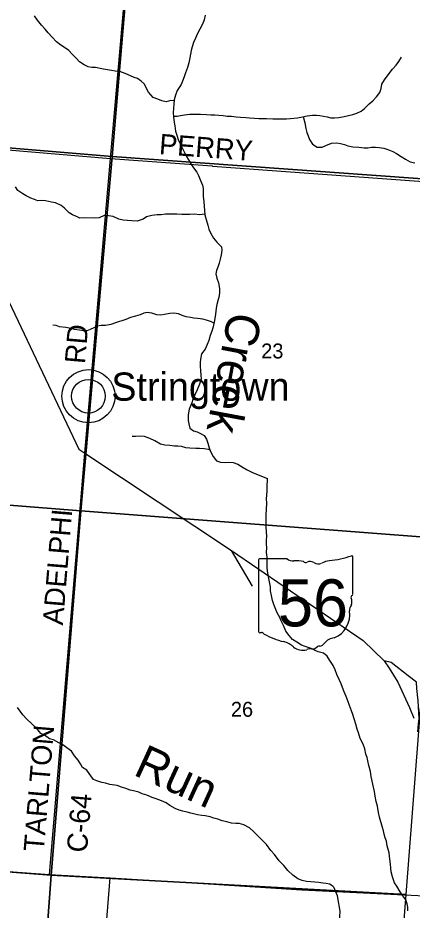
# Model space of a CAD drawing. Extents: x 1643459 to 2064572, y 425441 to 780708.
# Drawn here: x 1890096 to 1895923, y 540058 to 553249 of the extents above; entities that cross this region are included whole.
import ezdxf

# ---------------------------------------------------------------- set-up
doc = ezdxf.new("R2010")
doc.units = 0
for name, color, linetype in [('GE_P_Alignment_100_Curve_Data', 7, 'Continuous'), ('GM_X_Adjacent_County', 7, 'Continuous'), ('GM_X_Interchange_Ramps', 7, 'Continuous'), ('GM_X_Major_River', 7, 'Continuous'), ('GM_X_Major_River_Text', 7, 'Continuous'), ('GM_X_Minor_Lake', 7, 'Continuous'), ('GM_X_Rail_Line', 7, 'Continuous'), ('GM_X_Section_Text', 7, 'Continuous'), ('GM_X_State_Route', 7, 'Continuous'), ('GM_X_State_Shield', 7, 'Continuous'), ('GM_X_Township_ROW', 7, 'Continuous'), ('GM_X_Unincorporated_Text', 7, 'Continuous'), ('GM_X_US_Route', 7, 'Continuous'), ('PM_P_Cells', 7, 'Continuous'), ('RD_X_Text', 7, 'Continuous'), ('ST_Details', 7, 'Continuous')]:
    doc.layers.add(name, color=color, linetype=linetype)

msp = doc.modelspace()

# ---------------------------------------------------------------- linework, layer by layer
at = {"layer": 'GE_P_Alignment_100_Curve_Data'}
for radius in [393, 249]:
    msp.add_circle((1891139, 547656), radius, dxfattribs=at)
at = {"layer": 'GM_X_Major_River_Text'}
for points in [[(1888305, 551438), (1891467, 551170)], [(1891467, 551170), (1892970, 551059), (1892972, 551058)], [(1892972, 551058), (1901848, 550410)], [(1893566, 544847), (1893251, 545376)]]:
    msp.add_lwpolyline(points, dxfattribs=at)
at = {"layer": 'GM_X_Minor_Lake'}
for points in [[(1891088, 546815), (1891088, 546815), (1891467, 551170), (1891853, 555616)], [(1890566, 540586), (1891088, 546815)], [(1896005, 542692), (1896018, 542807), (1896027, 542889), (1896010, 543154), (1895992, 543336), (1895987, 543429), (1895862, 543523), (1895613, 543717), (1895512, 543746)], [(1877545, 541541), (1882763, 541167), (1885378, 540966), (1890566, 540586), (1891458, 540534), (1891546, 540529), (1892911, 540445), (1894292, 540358), (1896111, 540272)], [(1891039, 535264), (1891458, 540534)]]:
    msp.add_lwpolyline(points, dxfattribs=at)
at = {"layer": 'GM_X_Rail_Line'}
msp.add_line((1891139, 547656), (1891139, 547656), dxfattribs=at)
at = {"layer": 'GM_X_State_Route'}
for points in [[(1886800, 556947), (1891943, 556530), (1891491, 551199), (1886336, 551627)], [(1891943, 556530), (1897162, 556078), (1896690, 550827), (1891491, 551199)], [(1891491, 551199), (1891025, 545962), (1885858, 546368), (1886336, 551627)], [(1896690, 550827), (1896241, 545563), (1891025, 545962), (1891491, 551199)], [(1885858, 546368), (1891025, 545962), (1890589, 540577), (1885382, 540977)], [(1891025, 545962), (1896241, 545563), (1895832, 540288), (1890589, 540577)], [(1885382, 540977), (1890589, 540577), (1890205, 535356), (1890115, 535362), (1884902, 535726)], [(1890589, 540577), (1895832, 540288), (1895415, 535000), (1895294, 535008), (1890205, 535356)]]:
    msp.add_lwpolyline(points, close=True, dxfattribs=at)
at = {"layer": 'GM_X_Unincorporated_Text'}
for points in [[(1892865, 553289), (1892851, 553219), (1892828, 553165), (1892786, 553081), (1892753, 553019), (1892719, 552949), (1892690, 552885), (1892670, 552821), (1892656, 552765), (1892645, 552713), (1892637, 552657), (1892623, 552585), (1892601, 552517), (1892574, 552435), (1892552, 552379), (1892527, 552315), (1892509, 552265), (1892450, 552177), (1892426, 552107), (1892408, 552039), (1892400, 551975), (1892395, 551912), (1892393, 551844), (1892395, 551788), (1892407, 551702), (1892415, 551652), (1892427, 551573), (1892445, 551517), (1892467, 551453), (1892495, 551386), (1892527, 551320), (1892554, 551269), (1892582, 551211), (1892616, 551149), (1892654, 551090), (1892692, 551034), (1892739, 550967), (1892765, 550917), (1892795, 550846), (1892823, 550776), (1892833, 550726), (1892835, 550674), (1892837, 550615), (1892845, 550531), (1892851, 550467), (1892855, 550399), (1892858, 550337), (1892879, 550266), (1892905, 550182), (1892919, 550125), (1892943, 550069), (1892987, 549993), (1893039, 549934), (1893104, 549865), (1893112, 549813), (1893102, 549745), (1893085, 549683), (1893069, 549623), (1893053, 549565), (1893030, 549513), (1893022, 549463), (1893036, 549400), (1893060, 549334), (1893076, 549250), (1893076, 549200), (1893070, 549137), (1893056, 549083), (1893039, 549011), (1893025, 548955), (1893015, 548871), (1893001, 548777), (1892980, 548683), (1892962, 548619), (1892937, 548551), (1892917, 548481), (1892893, 548421), (1892862, 548351), (1892810, 548283), (1892793, 548205), (1892791, 548153), (1892791, 548098), (1892797, 548030), (1892801, 547968), (1892807, 547908), (1892782, 547836), (1892746, 547752), (1892713, 547676), (1892681, 547608)], [(1892681, 547608), (1892665, 547558), (1892626, 547466), (1892612, 547380), (1892614, 547299), (1892622, 547247), (1892638, 547183), (1892692, 547142), (1892744, 547128), (1892797, 547106), (1892847, 547075), (1892882, 547021), (1892904, 546960), (1892924, 546892), (1892944, 546838), (1892980, 546765), (1893030, 546701), (1893091, 546682), (1893158, 546678), (1893212, 546683), (1893279, 546675), (1893349, 546650), (1893426, 546604), (1893485, 546569), (1893545, 546536), (1893597, 546512), (1893784, 546439)], [(1895027, 543007), (1894999, 543083), (1894975, 543153), (1894947, 543216), (1894920, 543284), (1894896, 543350), (1894872, 543406), (1894846, 543467), (1894812, 543541), (1894784, 543613), (1894756, 543675), (1894706, 543750), (1894669, 543814), (1894611, 543857), (1894535, 543877), (1894479, 543903), (1894429, 543924), (1894340, 543954), (1894290, 543974), (1894218, 544019), (1894154, 544061), (1894105, 544116), (1894055, 544184), (1894023, 544266), (1893989, 544333), (1893967, 544383), (1893929, 544451), (1893907, 544505), (1893879, 544576), (1893859, 544638), (1893844, 544708), (1893830, 544778), (1893828, 544838), (1893820, 544889), (1893806, 544959), (1893790, 545039), (1893782, 545115), (1893779, 545179), (1893779, 545276), (1893773, 545344), (1893775, 545412), (1893773, 545472), (1893771, 545530), (1893774, 545586), (1893772, 545650), (1893768, 545723), (1893768, 545915), (1893769, 545971), (1893775, 546083), (1893773, 546135), (1893775, 546198), (1893779, 546254), (1893781, 546306), (1893784, 546439)], [(1895859, 540046), (1895859, 540100), (1895849, 540151), (1895832, 540209), (1895786, 540269), (1895748, 540327), (1895696, 540412), (1895662, 540462), (1895634, 540553), (1895612, 540627), (1895608, 540679), (1895604, 540739), (1895593, 540811), (1895583, 540908), (1895553, 541008), (1895543, 541076), (1895525, 541128), (1895511, 541180), (1895500, 541231), (1895486, 541281), (1895442, 541435), (1895426, 541502), (1895410, 541596), (1895392, 541666), (1895377, 541742), (1895369, 541810), (1895341, 541923), (1895317, 542035), (1895307, 542107), (1895284, 542198), (1895268, 542264), (1895256, 542314), (1895240, 542366), (1895224, 542441), (1895200, 542511), (1895156, 542597), (1895128, 542678), (1895113, 542732), (1895089, 542810), (1895067, 542886), (1895047, 542952), (1895027, 543007)]]:
    msp.add_lwpolyline(points, dxfattribs=at)
at = {"layer": 'GM_X_US_Route'}
for points in [[(1892406, 552023), (1892359, 552025), (1892286, 552008), (1892224, 552024), (1892165, 552045), (1892095, 552073), (1892026, 552148), (1891998, 552204), (1891968, 552269), (1891916, 552315), (1891863, 552354), (1891813, 552366), (1891762, 552392), (1891681, 552425), (1891601, 552454), (1891534, 552462), (1891482, 552471), (1891419, 552479), (1891364, 552490), (1891312, 552500), (1891241, 552513), (1891191, 552515), (1891136, 552527), (1891076, 552552), (1891007, 552599), (1890959, 552651), (1890898, 552712), (1890850, 552768), (1890800, 552799), (1890733, 552847), (1890667, 552896), (1890604, 552961), (1890546, 553027), (1890499, 553084), (1890443, 553142), (1890386, 553217), (1890344, 553277)], [(1892395, 551795), (1892397, 551794), (1892450, 551796), (1892500, 551805), (1892559, 551815), (1892638, 551824), (1892712, 551826), (1892793, 551823), (1892884, 551819), (1892947, 551816), (1893007, 551814), (1893064, 551811), (1893130, 551807), (1893187, 551798), (1893251, 551794), (1893322, 551787), (1893385, 551783), (1893465, 551776), (1893520, 551772), (1893591, 551765), (1893659, 551763), (1893716, 551762), (1893770, 551760), (1893863, 551757), (1894007, 551756), (1894065, 551758), (1894126, 551761), (1894231, 551773), (1894304, 551784), (1894372, 551800), (1894449, 551809), (1894508, 551811), (1894558, 551804), (1894613, 551794), (1894665, 551784), (1894722, 551771), (1894776, 551769), (1894841, 551774), (1894920, 551790), (1894982, 551803), (1895045, 551821), (1895106, 551839), (1895170, 551868), (1895221, 551910), (1895290, 551976), (1895344, 552023), (1895397, 552079), (1895444, 552145), (1895464, 552207), (1895476, 552269), (1895515, 552331), (1895569, 552409), (1895632, 552489), (1895685, 552548), (1895725, 552602), (1895766, 552670)], [(1894316, 551787), (1894316, 551770), (1894336, 551698), (1894352, 551615), (1894368, 551555), (1894384, 551505), (1894404, 551449), (1894448, 551380), (1894517, 551335), (1894592, 551339), (1894648, 551362), (1894729, 551398), (1894810, 551399), (1894862, 551393), (1894925, 551379), (1894975, 551358), (1895048, 551340), (1895133, 551335), (1895214, 551326), (1895268, 551328), (1895323, 551336), (1895383, 551337), (1895438, 551333), (1895506, 551322), (1895565, 551304), (1895636, 551275), (1895692, 551245), (1895759, 551198), (1895823, 551159), (1895896, 551119), (1895962, 551104)], [(1892858, 550345), (1892778, 550339), (1892707, 550346), (1892638, 550344), (1892576, 550343), (1892517, 550343), (1892444, 550348), (1892388, 550346), (1892327, 550346), (1892277, 550345), (1892212, 550339), (1892154, 550336), (1892077, 550326), (1891998, 550305), (1891947, 550273), (1891861, 550241), (1891778, 550246), (1891715, 550251), (1891650, 550257), (1891588, 550274), (1891507, 550312), (1891437, 550321), (1891370, 550327), (1891299, 550294), (1891226, 550290), (1891083, 550291), (1891014, 550290), (1890962, 550310), (1890905, 550339), (1890855, 550369), (1890784, 550436), (1890734, 550476), (1890651, 550515), (1890593, 550526), (1890506, 550546), (1890449, 550549), (1890393, 550545), (1890340, 550563), (1890290, 550584), (1890221, 550620), (1890171, 550649), (1890096, 550698), (1890062, 550752)], [(1892992, 548735), (1892960, 548755), (1892900, 548776), (1892829, 548796), (1892752, 548803), (1892696, 548811), (1892645, 548818), (1892585, 548830), (1892526, 548849), (1892468, 548873), (1892403, 548882), (1892344, 548876), (1892263, 548865), (1892209, 548853), (1892150, 548857), (1892076, 548882), (1892009, 548894), (1891959, 548883), (1891902, 548859), (1891837, 548840), (1891760, 548820), (1891692, 548788), (1891540, 548739), (1891471, 548716), (1891393, 548700), (1891326, 548699), (1891273, 548689), (1891166, 548642), (1891114, 548622), (1891061, 548623), (1891009, 548633), (1890932, 548644), (1890855, 548662), (1890805, 548673), (1890712, 548683), (1890661, 548700), (1890611, 548708)], [(1892937, 546856), (1892912, 546868), (1892847, 546879), (1892780, 546883), (1892724, 546885), (1892639, 546888), (1892580, 546895), (1892514, 546911), (1892461, 546917), (1892409, 546918), (1892344, 546926), (1892267, 546933), (1892205, 546947), (1892118, 546994), (1892045, 547033), (1891967, 547059), (1891906, 547064), (1891835, 547060), (1891785, 547061)], [(1894763, 540404), (1894705, 540443), (1894653, 540451), (1894603, 540457), (1894542, 540468), (1894486, 540470), (1894424, 540476), (1894364, 540483), (1894296, 540497), (1894232, 540523), (1894158, 540576), (1894086, 540642), (1894028, 540717), (1893956, 540787), (1893887, 540882), (1893833, 540942), (1893773, 541027), (1893695, 541101), (1893639, 541160), (1893579, 541220), (1893519, 541274), (1893437, 541321), (1893369, 541337), (1893315, 541340), (1893255, 541346), (1893185, 541362), (1893117, 541379), (1893051, 541405), (1892993, 541419), (1892937, 541440), (1892863, 541452), (1892813, 541456), (1892753, 541465), (1892654, 541491), (1892600, 541507), (1892532, 541522), (1892478, 541536), (1892420, 541560), (1892344, 541607), (1892288, 541643), (1892218, 541674), (1892142, 541702), (1892080, 541726), (1892004, 541757), (1891932, 541777), (1891882, 541800), (1891806, 541820), (1891754, 541834), (1891694, 541857), (1891630, 541877), (1891564, 541899), (1891456, 541918), (1891392, 541934), (1891338, 541944), (1891264, 541969), (1891214, 541991), (1891176, 542045), (1891114, 542126), (1891052, 542168), (1891024, 542219), (1890988, 542275), (1890932, 542341), (1890888, 542408), (1890820, 542456), (1890762, 542502), (1890700, 542533), (1890624, 542575), (1890566, 542590), (1890492, 542644), (1890434, 542672), (1890375, 542745), (1890299, 542819), (1890227, 542880), (1890171, 542946), (1890131, 542999), (1890091, 543055)], [(1894763, 540404), (1894814, 540276), (1894832, 540180), (1894844, 540103), (1894852, 540037), (1894848, 539967), (1894846, 539899), (1894843, 539827), (1894849, 539759), (1894857, 539688), (1894883, 539622), (1894919, 539568), (1894979, 539528), (1895043, 539481), (1895105, 539411), (1895127, 539352), (1895147, 539298), (1895164, 539244), (1895160, 539172), (1895142, 539104), (1895098, 539028), (1895058, 538937)]]:
    msp.add_lwpolyline(points, dxfattribs=at)
at = {"layer": 'RD_X_Text'}
msp.add_lwpolyline([(1880995, 552056), (1886302, 551599), (1888305, 551438), (1888926, 550537), (1889506, 549910), (1889875, 549245), (1890997, 546871), (1891088, 546815), (1893251, 545376), (1895197, 544046), (1895512, 543746), (1895582, 543637), (1895713, 543427), (1895886, 543052), (1895947, 542897)], dxfattribs=at)
at = {"layer": 'ST_Details'}
for p, q in [((1893653, 545235), (1893653, 544178)), ((1894075, 545253), (1893667, 545253)), ((1895045, 544727), (1895045, 545279)), ((1895045, 544727), (1895045, 544727))]:
    msp.add_line(p, q, dxfattribs=at)
for centre, radius, start, end in [((1893669, 545237), 16.1, 98.1301, 188.1301), ((1894172, 545376), 156, 231.6195, 271.1119), ((1894224, 544660), 562, 80.4867, 94.9883), ((1894351, 545243), 45.1, 219.7921, 297.1024), ((1894417, 545121), 93.8, 54.4667, 119.1411), ((1894538, 545288), 113, 233.8562, 294.8282), ((1894738, 544930), 297, 97.3462, 120.7689), ((1894549, 546694), 1476, 275.8445, 288.9065), ((1895030, 545282), 15.5, 351.8621, 97.738), ((1895042, 544686), 24, 107.944, 210.337), ((1894889, 544616), 144, 340.033, 23.6496), ((1895029, 544724), 16.6, 289.6038, 7.7341), ((1895101, 544495), 105, 136.8065, 186.9296), ((1894632, 544425), 369, 292.3089, 8.9858), ((1893669, 544176), 16.3, 171.9584, 258.3066), ((1893672, 544284), 124, 267.339, 280.6039), ((1893697, 544117), 44.8, 29.7484, 93.2717), ((1894262, 545067), 1066, 240.4129, 257.1985), ((1893945, 543704), 334, 47.1842, 75.836), ((1894532, 544076), 119, 282.8732, 323.2771), ((1894788, 543882), 202, 94.4031, 142.5768), ((1894305, 544112), 212, 230.7004, 286.2918), ((1894428, 543747), 174, 85.6951, 111.2099), ((1894443, 544033), 113, 268.777, 315.5493), ((1894545, 543931), 31.8, 65.7517, 132.6484)]:
    msp.add_arc(centre, radius, start, end, dxfattribs=at)

# ---------------------------------------------------------------- texts
at = {"layer": 'GM_X_Adjacent_County'}
for s, p in [('23', (1893692, 548214)), ('26', (1893244, 542917))]:
    msp.add_text(s, height=221, rotation=0, dxfattribs=at).set_placement(p)
at = {"layer": 'GM_X_Interchange_Ramps'}
msp.add_text('Run', height=500, rotation=335.4487, dxfattribs=at).set_placement((1891786, 542065))
at = {"layer": 'GM_X_Major_River'}
msp.add_text('PERRY', height=300, rotation=355.7479, dxfattribs=at).set_placement((1892177, 551236))
at = {"layer": 'GM_X_Section_Text'}
for s, rotation, p in [('RD', 85.0737, (1891087, 548127)), ('ADELPHI', 85.3168, (1890761, 544264)), ('TARLTON', 85.285, (1890479, 540915)), ('C-64', 85.208, (1891116, 540902))]:
    msp.add_text(s, height=300, rotation=rotation, dxfattribs=at).set_placement(p)
at = {"layer": 'GM_X_State_Shield'}
msp.add_text('Creek', height=500, rotation=259.4481, dxfattribs=at).set_placement((1893212, 548919))
at = {"layer": 'GM_X_Township_ROW'}
msp.add_text('Stringtown', height=417, rotation=0, dxfattribs=at).set_placement((1891477, 547589))
at = {"layer": 'PM_P_Cells'}
msp.add_text('56', height=1, rotation=0, dxfattribs=at).set_placement((1894082, 544564))
for s in ['s', 'r']:
    msp.add_text(s, height=1, dxfattribs=at).set_placement((1894334, 544636))
at = {"layer": 'ST_Details'}
msp.add_text('56', height=696.1, dxfattribs=at).set_placement((1893940, 544253))

doc.saveas('drawing.dxf')
